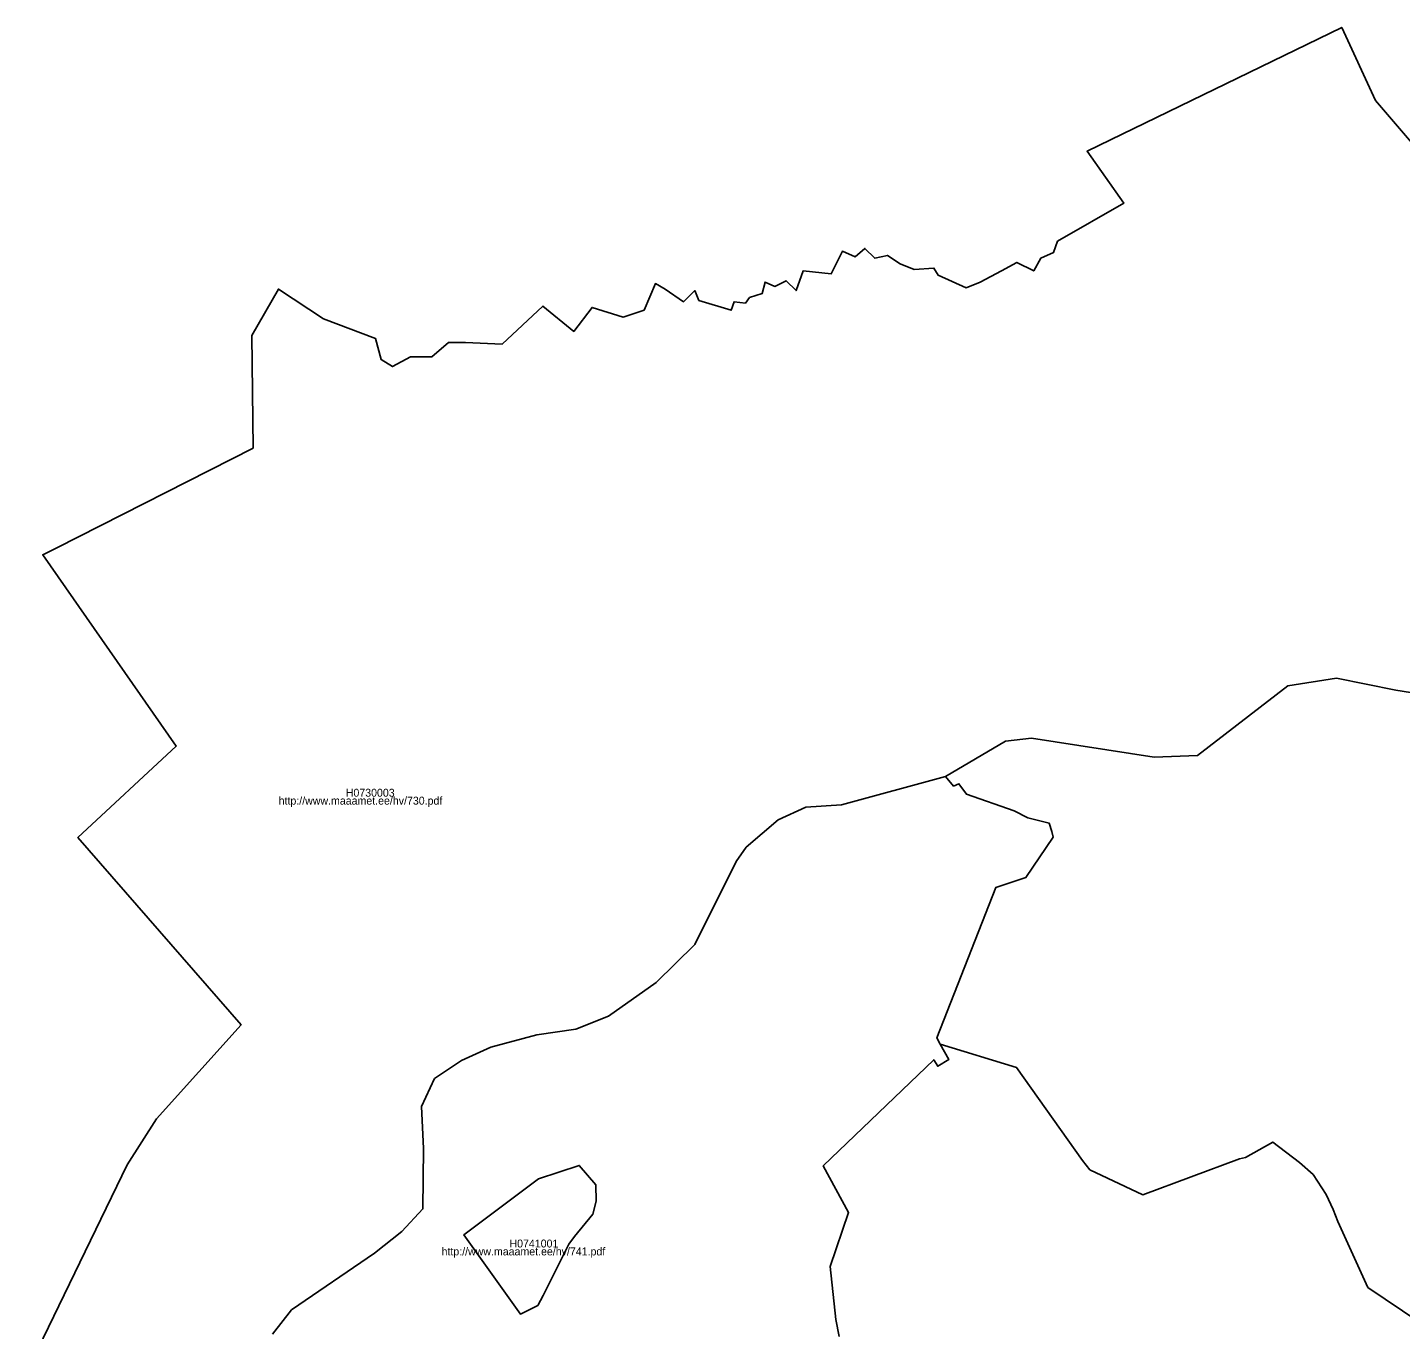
# Model space of a CAD drawing. Extents: x 369010 to 739155, y 6377141 to 6634081.
# Drawn here: x 536627 to 540961, y 6473768 to 6477879 of the extents above; entities that cross this region are included whole.
import ezdxf

# ---------------------------------------------------------------- set-up
doc = ezdxf.new("R2010")
doc.units = 0
for name, color, linetype in [('H_LINK', 7, 'Continuous'), ('H_PIIR', 7, 'Continuous'), ('H_TUNNUS', 7, 'Continuous')]:
    doc.layers.add(name, color=color, linetype=linetype)

msp = doc.modelspace()

# ---------------------------------------------------------------- linework, layer by layer
at = {"layer": 'H_PIIR'}
for points in [[(541711.9301, 6476680.03), (540881.74, 6477648.33), (540775.2599, 6477878.7199), (539971.7101, 6477487.85), (540087.1301, 6477323.5), (539878.47, 6477203.5699), (539865.15, 6477168.04), (539825.2001, 6477150.27), (539803, 6477110.3001), (539749.73, 6477136.95), (539700.89, 6477110.3001), (539634.3, 6477074.76), (539589.9, 6477056.9899), (539501.11, 6477096.9701), (539487.79, 6477119.18), (539425.64, 6477114.7399), (539381.24, 6477132.5), (539341.29, 6477159.1599), (539301.33, 6477150.27), (539270.26, 6477181.36), (539239.18, 6477154.7101), (539199.22, 6477172.4799), (539163.71, 6477101.4099), (539074.9199, 6477110.3001), (539052.72, 6477048.11), (539021.64, 6477079.2), (538986.1299, 6477061.44), (538955.0501, 6477074.76), (538946.17, 6477039.2301), (538906.21, 6477025.8999), (538892.9, 6477008.1401), (538857.3799, 6477012.5799), (538848.5, 6476985.93), (538746.39, 6477017.02), (538733.07, 6477048.11), (538697.5599, 6477012.5799), (538639.84, 6477052.5501), (538608.7699, 6477070.3199), (538573.24, 6476985.93), (538506.6499, 6476963.7201), (538408.98, 6476994.8101), (538351.27, 6476919.3001), (538253.6, 6476999.25), (538124.85, 6476879.3199), (538009.4201, 6476883.77), (537956.1499, 6476883.77), (537902.88, 6476839.35), (537836.2801, 6476839.35), (537778.5701, 6476808.26), (537743.05, 6476830.47), (537725.29, 6476897.09), (537561.0301, 6476959.28), (537418.9699, 6477052.5501), (537334.62, 6476905.9801), (537339.06, 6476550.6301), (536719.32, 6476236.29), (536674.93, 6476214.0799), (537096.68, 6475609.9999), (536785.91, 6475321.28), (537300.9001, 6474730.53), (537034.53, 6474432.9299), (536941.9801, 6474287.8), (536626.7799, 6473639.31)], [(536626.7799, 6473639.31), (536941.9801, 6474287.8), (537034.53, 6474432.9299), (537300.9001, 6474730.53), (536785.91, 6475321.28), (537096.68, 6475609.9999), (536674.93, 6476214.0799), (536719.32, 6476236.29), (537339.06, 6476550.6301), (537334.62, 6476905.9801), (537418.9699, 6477052.5501), (537561.0301, 6476959.28), (537725.29, 6476897.09), (537743.05, 6476830.47), (537778.5701, 6476808.26), (537836.2801, 6476839.35), (537902.88, 6476839.35), (537956.1499, 6476883.77), (538009.4201, 6476883.77), (538124.85, 6476879.3199), (538253.6, 6476999.25), (538351.27, 6476919.3001), (538408.98, 6476994.8101), (538506.6499, 6476963.7201), (538573.24, 6476985.93), (538608.7699, 6477070.3199), (538639.84, 6477052.5501), (538697.5599, 6477012.5799), (538733.07, 6477048.11), (538746.39, 6477017.02), (538848.5, 6476985.93), (538857.3799, 6477012.5799), (538892.9, 6477008.1401), (538906.21, 6477025.8999), (538946.17, 6477039.2301), (538955.0501, 6477074.76), (538986.1299, 6477061.44), (539021.64, 6477079.2), (539052.72, 6477048.11), (539074.9199, 6477110.3001), (539163.71, 6477101.4099), (539199.22, 6477172.4799), (539239.18, 6477154.7101), (539270.26, 6477181.36), (539301.33, 6477150.27), (539341.29, 6477159.1599), (539381.24, 6477132.5), (539425.64, 6477114.7399), (539487.79, 6477119.18), (539501.11, 6477096.9701), (539589.9, 6477056.9899), (539634.3, 6477074.76), (539700.89, 6477110.3001), (539749.73, 6477136.95), (539803, 6477110.3001), (539825.2001, 6477150.27), (539865.15, 6477168.04), (539878.47, 6477203.5699), (540087.1301, 6477323.5), (539971.7101, 6477487.85), (540775.2599, 6477878.7199), (540881.74, 6477648.33), (541711.9301, 6476680.03)], [(541105.12, 6475761.37), (540945.94, 6475786.6801), (540758.6601, 6475824.31), (540605.39, 6475800.75), (540320.2001, 6475580.1201), (540183.27, 6475575.22), (539796, 6475634.8901), (539714.2199, 6475625.0701), (539524.17, 6475514.06), (539195.93, 6475425.03), (539083.35, 6475417.72), (538996.6601, 6475376.81), (538895.6601, 6475291.4499), (538863.9301, 6475245.3299), (538733.63, 6474983.4401), (538610.95, 6474863.28), (538460.35, 6474757.51), (538357.97, 6474716.8901), (538234.4401, 6474698.27), (538089.76, 6474659.35), (537996.7001, 6474617.0399), (537911.2399, 6474560.34), (537870.63, 6474472.3401), (537877.4, 6474339.4899), (537874.8599, 6474149.0999), (537808.0201, 6474078.02), (537722.5701, 6474009.4799), (537460.28, 6473830.0901), (537400.21, 6473753.9401)], [(541021.43, 6473790.3201), (540857.2899, 6473901.17), (540762.53, 6474109.3301), (540748.1499, 6474147.4101), (540726.15, 6474193.95), (540684.6899, 6474257.41), (540642.39, 6474295.49), (540557.7799, 6474359.8001), (540471.48, 6474311.57), (540452.8701, 6474307.34), (540147.98, 6474192.8699), (539980.1999, 6474272.5599), (539956.6199, 6474301.7), (539749.21, 6474595.87), (539507.8001, 6474668.66), (539496.8001, 6474688.96), (539683.7801, 6475163.67), (539778.54, 6475194.98), (539864.8399, 6475322.7601), (539859.89, 6475340.0101), (539851.7101, 6475367.0099), (539784.6499, 6475383.3701), (539740.8901, 6475405.2601), (539590.41, 6475458.43), (539566.6901, 6475491.1599), (539550.3399, 6475483.8), (539524.17, 6475514.06), (539714.2199, 6475625.0701), (539796, 6475634.8901), (540183.27, 6475575.22), (540320.2001, 6475580.1201), (540605.39, 6475800.75), (540758.6601, 6475824.31), (540945.94, 6475786.6801), (541105.12, 6475761.37)], [(537400.21, 6473753.9401), (537460.28, 6473830.0901), (537722.5701, 6474009.4799), (537808.0201, 6474078.02), (537874.8599, 6474149.0999), (537877.4, 6474339.4899), (537870.63, 6474472.3401), (537911.2399, 6474560.34), (537996.7001, 6474617.0399), (538089.76, 6474659.35), (538234.4401, 6474698.27), (538357.97, 6474716.8901), (538460.35, 6474757.51), (538610.95, 6474863.28), (538733.63, 6474983.4401), (538863.9301, 6475245.3299), (538895.6601, 6475291.4499), (538996.6601, 6475376.81), (539083.35, 6475417.72), (539195.93, 6475425.03), (539524.17, 6475514.06), (539550.3399, 6475483.8), (539566.6901, 6475491.1599), (539590.41, 6475458.43), (539740.8901, 6475405.2601), (539784.6499, 6475383.3701), (539851.7101, 6475367.0099), (539859.89, 6475340.0101), (539864.8399, 6475322.7601), (539778.54, 6475194.98), (539683.7801, 6475163.67), (539496.8001, 6474688.96), (539507.8001, 6474668.66), (539534.8701, 6474620.4199), (539500.1799, 6474599.2701), (539487.4899, 6474619.58), (539138.9, 6474284.49), (539218.44, 6474137.26), (539160.06, 6473967.17), (539178.67, 6473799.63), (539188.8764, 6473745.9075)], [(539188.8764, 6473745.9075), (539178.67, 6473799.63), (539160.06, 6473967.17), (539218.44, 6474137.26), (539138.9, 6474284.49), (539487.4899, 6474619.58), (539500.1799, 6474599.2701), (539534.8701, 6474620.4199), (539507.8001, 6474668.66), (539749.21, 6474595.87), (539956.6199, 6474301.7), (539980.1999, 6474272.5599), (540147.98, 6474192.8699), (540452.8701, 6474307.34), (540471.48, 6474311.57), (540557.7799, 6474359.8001), (540642.39, 6474295.49), (540684.6899, 6474257.41), (540726.15, 6474193.95), (540748.1499, 6474147.4101), (540762.53, 6474109.3301), (540857.2899, 6473901.17), (541021.43, 6473790.3201)]]:
    msp.add_lwpolyline(points, dxfattribs=at)
for points in [[(538353.8601, 6474062.14), (538411.69, 6474132.12), (538421.61, 6474173.4401), (538420.51, 6474224.6899), (538368.64, 6474286.04), (538239.95, 6474243.57), (538003.68, 6474067.0699), (538183.22, 6473816.44), (538237.5, 6473843.59), (538254.6301, 6473876.03), (538336.15, 6474037.2701)], [(538353.8601, 6474062.14), (538336.15, 6474037.2701), (538254.6301, 6473876.03), (538237.5, 6473843.59), (538183.22, 6473816.44), (538003.68, 6474067.0699), (538239.95, 6474243.57), (538368.64, 6474286.04), (538420.51, 6474224.6899), (538421.61, 6474173.4401), (538411.69, 6474132.12)]]:
    msp.add_lwpolyline(points, close=True, dxfattribs=at)

# ---------------------------------------------------------------- texts
at = {"layer": 'H_LINK'}
for s, rotation, p in [('http://www.maaamet.ee/hv/730.pdf', 0, (537419.6663, 6475425.2993)), ('http://www.maaamet.ee/hv/741.pdf', 360, (537933.9203, 6474002.1652))]:
    msp.add_text(s, height=25, rotation=rotation, dxfattribs=at).set_placement(p)
at = {"layer": 'H_TUNNUS'}
for s, rotation, p in [('H0730003', 0, (537631.5208, 6475450.2993)), ('H0741001', 360, (538148.2743, 6474027.1652))]:
    msp.add_text(s, height=25, rotation=rotation, dxfattribs=at).set_placement(p)

doc.saveas('drawing.dxf')
